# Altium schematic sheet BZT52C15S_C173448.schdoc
size 127 x 101 mm
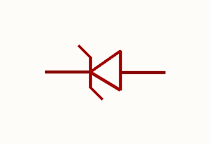
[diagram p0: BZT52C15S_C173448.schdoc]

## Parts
D?  bzt52c15s_c173448  [SOD-323_L1.8-W1.3-LS2.5-RD]  (value not drawn)

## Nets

Not connected (* = marked no-connect by the designer): D? 1 2

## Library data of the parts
D? = bzt52c15s_c173448: 二极管配置:1个独立式;稳压值(标称值):15V;稳压值(范围):13.8V~15.6V;耗散功率(Pd):200mW;; Manufacturer: MDD(辰达半导体); AddInBom: yes; ModelId: db63db13d9e342eb939127d413d6200b; ModelTransform: 104.3305,51.181,0,0,0,0,0,-0.004,0; Diode Configuration: 1个独立式; Zener Voltage(Nom): 15V; Reverse Leakage Current (Ir): 100nA@11V; Pd - Power Dissipation: 200mW; Impedance(Zzt): 40Ω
